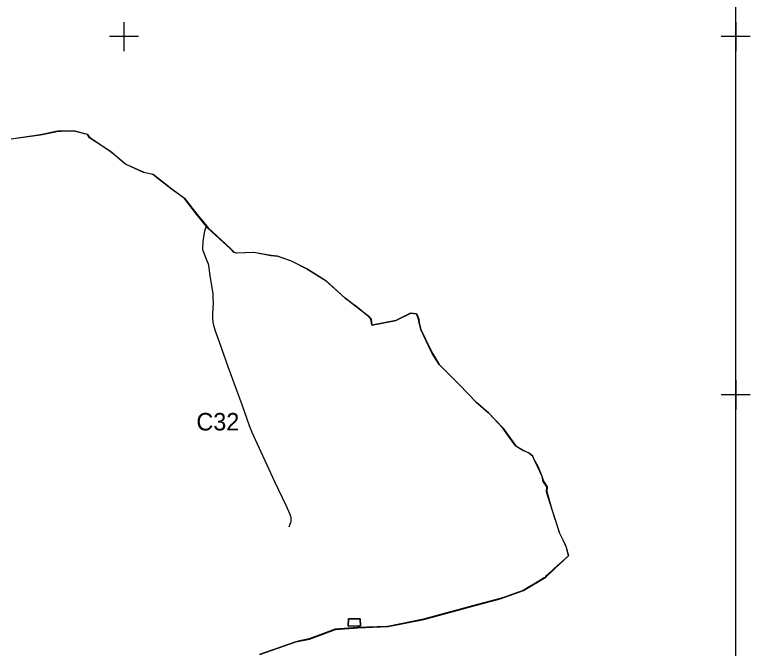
# Model space of a CAD drawing. Extents: x -478490 to -472450, y -1118050 to -1109550.
# Drawn here: x -474975 to -472450, y -1115900 to -1113725 of the extents above; entities that cross this region are included whole.
import ezdxf

# ---------------------------------------------------------------- set-up
doc = ezdxf.new("R2010")
doc.units = 0
for name, color, linetype in [('hranice kú', 7, 'Continuous'), ('Implicitní', 7, 'Continuous'), ('ObPÚ', 7, 'Continuous')]:
    doc.layers.add(name, color=color, linetype=linetype)

msp = doc.modelspace()

# ---------------------------------------------------------------- linework, layer by layer
at = {"layer": 'hranice kú'}
for p, q in [((-474772, -1114123.9), (-474828.5, -1114124.9)), ((-474725.6, -1114136), (-474772, -1114123.9)), ((-474886, -1114137.7), (-474987.2, -1114152.5)), ((-474828.5, -1114124.9), (-474886, -1114137.7)), ((-474718.2, -1114148.1), (-474725.6, -1114136)), ((-474646.3, -1114194.8), (-474718.2, -1114148.1)), ((-474595.2, -1114238.2), (-474646.3, -1114194.8)), ((-474533.5, -1114266.7), (-474595.2, -1114238.2)), ((-474500.2, -1114273.4), (-474533.5, -1114266.7)), ((-474436, -1114323.8), (-474500.2, -1114273.4)), ((-474392.1, -1114355.8), (-474436, -1114323.8)), ((-474351.1, -1114410.2), (-474392.1, -1114355.8)), ((-474312.1, -1114458.1), (-474351.1, -1114410.2)), ((-474234.1, -1114528.4), (-474312.1, -1114458.1)), ((-474222.7, -1114541.2), (-474234.1, -1114528.4)), ((-474214.6, -1114544.2), (-474222.7, -1114541.2)), ((-474155.1, -1114541.5), (-474214.6, -1114544.2)), ((-474095.2, -1114552.2), (-474155.1, -1114541.5)), ((-474072.7, -1114554.2), (-474095.2, -1114552.2)), ((-474025.3, -1114571.1), (-474072.7, -1114554.2)), ((-473972.5, -1114598), (-474025.3, -1114571.1)), ((-473907.3, -1114639), (-473972.5, -1114598)), ((-473840.6, -1114698.6), (-473907.3, -1114639)), ((-473807, -1114724.1), (-473840.6, -1114698.6)), ((-473760, -1114761.1), (-473807, -1114724.1)), ((-473616.5, -1114749.9), (-473666.9, -1114774.4)), ((-473595.9, -1114752.2), (-473616.5, -1114749.9)), ((-473588.6, -1114770.3), (-473595.9, -1114752.2)), ((-473752.6, -1114770.7), (-473760, -1114761.1)), ((-473748.8, -1114790.3), (-473752.6, -1114770.7)), ((-473666.9, -1114774.4), (-473748.8, -1114790.3)), ((-473587, -1114782.1), (-473588.6, -1114770.3)), ((-473581.1, -1114806.2), (-473587, -1114782.1)), ((-473565.4, -1114840.2), (-473581.1, -1114806.2)), ((-473541.9, -1114887.9), (-473565.4, -1114840.2)), ((-473518.4, -1114925.3), (-473541.9, -1114887.9)), ((-473447.1, -1114996.9), (-473518.4, -1114925.3)), ((-473390.3, -1115055.8), (-473447.1, -1114996.9)), ((-473347.2, -1115093.3), (-473390.3, -1115055.8)), ((-473299.1, -1115144.4), (-473347.2, -1115093.3)), ((-473261.8, -1115197.2), (-473299.1, -1115144.4)), ((-473254.4, -1115206.6), (-473261.8, -1115197.2)), ((-473230.6, -1115220.7), (-473254.4, -1115206.6)), ((-473209.4, -1115230.8), (-473230.6, -1115220.7)), ((-473197.9, -1115239.5), (-473209.4, -1115230.8)), ((-473191.9, -1115251.7), (-473197.9, -1115239.5)), ((-473180.1, -1115275.5), (-473191.9, -1115251.7)), ((-473165, -1115309.9), (-473180.1, -1115275.5)), ((-473160.6, -1115327.4), (-473165, -1115309.9)), ((-473148.9, -1115345.9), (-473160.6, -1115327.4)), ((-473149.2, -1115363.1), (-473148.9, -1115345.9)), ((-473130.7, -1115424.9), (-473149.2, -1115363.1)), ((-473119.6, -1115455.5), (-473130.7, -1115424.9)), ((-473104.5, -1115503.7), (-473119.6, -1115455.5)), ((-473092.7, -1115529.3), (-473104.5, -1115503.7)), ((-473081.3, -1115554.2), (-473092.7, -1115529.3)), ((-473073.6, -1115582.8), (-473081.3, -1115554.2)), ((-473122.6, -1115627.2), (-473073.6, -1115582.8)), ((-473152.2, -1115655.7), (-473122.6, -1115627.2)), ((-473228.9, -1115701.8), (-473152.2, -1115655.7)), ((-473308.3, -1115730.5), (-473228.9, -1115701.8)), ((-473402.8, -1115755.4), (-473308.3, -1115730.5)), ((-473570.6, -1115801.1), (-473402.8, -1115755.4)), ((-473693.7, -1115825.7), (-473570.6, -1115801.1)), ((-473963.2, -1115868.4), (-473874.4, -1115835.4)), ((-473874.4, -1115835.4), (-473797.2, -1115830.4)), ((-473797.2, -1115830.4), (-473693.7, -1115825.7)), ((-474134.2, -1115921.7), (-474010.2, -1115878.5)), ((-474010.2, -1115878.5), (-473963.2, -1115868.4))]:
    msp.add_line(p, q, dxfattribs=at)
at = {"layer": 'Implicitní'}
for p, q in [((-474600.1, -1113750.1), (-474600.1, -1113850.1)), ((-474600.1, -1113750.1), (-474600.1, -1113850.1)), ((-474600.1, -1113750.1), (-474600.1, -1113850.1)), ((-474600.1, -1113750.1), (-474600.1, -1113850.1)), ((-474600.1, -1113750.1), (-474600.1, -1113850.1)), ((-474600.1, -1113750.1), (-474600.1, -1113850.1)), ((-474600.1, -1113750.1), (-474600.1, -1113850.1)), ((-474600.1, -1113750.1), (-474600.1, -1113850.1)), ((-474600.1, -1113750.1), (-474600.1, -1113850.1)), ((-474600.1, -1113750.1), (-474600.1, -1113850.1)), ((-474600.1, -1113750.1), (-474600.1, -1113850.1)), ((-474600.1, -1113750.1), (-474600.1, -1113850.1)), ((-474600.1, -1113750.1), (-474600.1, -1113850.1)), ((-474600.1, -1113750.1), (-474600.1, -1113850.1)), ((-474600.1, -1113750.1), (-474600.1, -1113850.1)), ((-474600.1, -1113750.1), (-474600.1, -1113850.1)), ((-474600.1, -1113750.1), (-474600.1, -1113850.1)), ((-474600.1, -1113750.1), (-474600.1, -1113850.1)), ((-474600.1, -1113750.1), (-474600.1, -1113850.1)), ((-474600.1, -1113750.1), (-474600.1, -1113850.1)), ((-474600.1, -1113750.1), (-474600.1, -1113850.1)), ((-474600.1, -1113750.1), (-474600.1, -1113850.1)), ((-474600.1, -1113750.1), (-474600.1, -1113850.1)), ((-474600.1, -1113750.1), (-474600.1, -1113850.1)), ((-474600.1, -1113750.1), (-474600.1, -1113850.1)), ((-474600.1, -1113750.1), (-474600.1, -1113850.1)), ((-474600.1, -1113750.1), (-474600.1, -1113850.1)), ((-474600.1, -1113750.1), (-474600.1, -1113850.1)), ((-474600.1, -1113750.1), (-474600.1, -1113850.1)), ((-474600.1, -1113750.1), (-474600.1, -1113850.1)), ((-474600.1, -1113750.1), (-474600.1, -1113850.1)), ((-474600.1, -1113750.1), (-474600.1, -1113850.1)), ((-474600.1, -1113750.1), (-474600.1, -1113850.1)), ((-474600.1, -1113750.1), (-474600.1, -1113850.1)), ((-474600.1, -1113750.1), (-474600.1, -1113850.1)), ((-474600.1, -1113750.1), (-474600.1, -1113850.1)), ((-474600.1, -1113750.1), (-474600.1, -1113850.1)), ((-474600.1, -1113750.1), (-474600.1, -1113850.1)), ((-474600.1, -1113750.1), (-474600.1, -1113850.1)), ((-474600.1, -1113750.1), (-474600.1, -1113850.1)), ((-474600.1, -1113750.1), (-474600.1, -1113850.1)), ((-474600.1, -1113750.1), (-474600.1, -1113850.1)), ((-474600.1, -1113750.1), (-474600.1, -1113850.1)), ((-474600.1, -1113750.1), (-474600.1, -1113850.1)), ((-474600.1, -1113750.1), (-474600.1, -1113850.1)), ((-474600.1, -1113750.1), (-474600.1, -1113850.1)), ((-474600.1, -1113750.1), (-474600.1, -1113850.1)), ((-474600.1, -1113750.1), (-474600.1, -1113850.1)), ((-474600.1, -1113750.1), (-474600.1, -1113850.1)), ((-474600.1, -1113750.1), (-474600.1, -1113850.1)), ((-474600.1, -1113750.1), (-474600.1, -1113850.1)), ((-474600.1, -1113750.1), (-474600.1, -1113850.1)), ((-474600.1, -1113750.1), (-474600.1, -1113850.1)), ((-474600.1, -1113750.1), (-474600.1, -1113850.1)), ((-474600.1, -1113750.1), (-474600.1, -1113850.1)), ((-474600.1, -1113750.1), (-474600.1, -1113850.1)), ((-474600.1, -1113750.1), (-474600.1, -1113850.1)), ((-474600.1, -1113750.1), (-474600.1, -1113850.1)), ((-474600.1, -1113750.1), (-474600.1, -1113850.1)), ((-474600.1, -1113750.1), (-474600.1, -1113850.1)), ((-474600.1, -1113750.1), (-474600.1, -1113850.1)), ((-472500.1, -1113750.1), (-472500.1, -1113850.1)), ((-472500.1, -1113750.1), (-472500.1, -1113850.1)), ((-472500.1, -1113750.1), (-472500.1, -1113850.1)), ((-472500.1, -1113750.1), (-472500.1, -1113850.1)), ((-472500.1, -1113750.1), (-472500.1, -1113850.1)), ((-472500.1, -1113750.1), (-472500.1, -1113850.1)), ((-472500.1, -1113750.1), (-472500.1, -1113850.1)), ((-472500.1, -1113750.1), (-472500.1, -1113850.1)), ((-472500.1, -1113750.1), (-472500.1, -1113850.1)), ((-472500.1, -1113750.1), (-472500.1, -1113850.1)), ((-472500.1, -1113750.1), (-472500.1, -1113850.1)), ((-472500.1, -1113750.1), (-472500.1, -1113850.1)), ((-472500.1, -1113750.1), (-472500.1, -1113850.1)), ((-472500.1, -1113750.1), (-472500.1, -1113850.1)), ((-472500.1, -1113750.1), (-472500.1, -1113850.1)), ((-472500.1, -1113750.1), (-472500.1, -1113850.1)), ((-472500.1, -1113750.1), (-472500.1, -1113850.1)), ((-472500.1, -1113750.1), (-472500.1, -1113850.1)), ((-472500.1, -1113750.1), (-472500.1, -1113850.1)), ((-472500.1, -1113750.1), (-472500.1, -1113850.1)), ((-472500.1, -1113750.1), (-472500.1, -1113850.1)), ((-472500.1, -1113750.1), (-472500.1, -1113850.1)), ((-472500.1, -1113750.1), (-472500.1, -1113850.1)), ((-472500.1, -1113750.1), (-472500.1, -1113850.1)), ((-474550.1, -1113800.1), (-474650.1, -1113800.1)), ((-474550.1, -1113800.1), (-474650.1, -1113800.1)), ((-474550.1, -1113800.1), (-474650.1, -1113800.1)), ((-474550.1, -1113800.1), (-474650.1, -1113800.1)), ((-474550.1, -1113800.1), (-474650.1, -1113800.1)), ((-474550.1, -1113800.1), (-474650.1, -1113800.1)), ((-474550.1, -1113800.1), (-474650.1, -1113800.1)), ((-474550.1, -1113800.1), (-474650.1, -1113800.1)), ((-474550.1, -1113800.1), (-474650.1, -1113800.1)), ((-474550.1, -1113800.1), (-474650.1, -1113800.1)), ((-474550.1, -1113800.1), (-474650.1, -1113800.1)), ((-474550.1, -1113800.1), (-474650.1, -1113800.1)), ((-474550.1, -1113800.1), (-474650.1, -1113800.1)), ((-474550.1, -1113800.1), (-474650.1, -1113800.1)), ((-474550.1, -1113800.1), (-474650.1, -1113800.1)), ((-474550.1, -1113800.1), (-474650.1, -1113800.1)), ((-474550.1, -1113800.1), (-474650.1, -1113800.1)), ((-474550.1, -1113800.1), (-474650.1, -1113800.1)), ((-474550.1, -1113800.1), (-474650.1, -1113800.1)), ((-474550.1, -1113800.1), (-474650.1, -1113800.1)), ((-474550.1, -1113800.1), (-474650.1, -1113800.1)), ((-474550.1, -1113800.1), (-474650.1, -1113800.1)), ((-474550.1, -1113800.1), (-474650.1, -1113800.1)), ((-474550.1, -1113800.1), (-474650.1, -1113800.1)), ((-474550.1, -1113800.1), (-474650.1, -1113800.1)), ((-474550.1, -1113800.1), (-474650.1, -1113800.1)), ((-474550.1, -1113800.1), (-474650.1, -1113800.1)), ((-474550.1, -1113800.1), (-474650.1, -1113800.1)), ((-474550.1, -1113800.1), (-474650.1, -1113800.1)), ((-474550.1, -1113800.1), (-474650.1, -1113800.1)), ((-474550.1, -1113800.1), (-474650.1, -1113800.1)), ((-474550.1, -1113800.1), (-474650.1, -1113800.1)), ((-474550.1, -1113800.1), (-474650.1, -1113800.1)), ((-474550.1, -1113800.1), (-474650.1, -1113800.1)), ((-474550.1, -1113800.1), (-474650.1, -1113800.1)), ((-474550.1, -1113800.1), (-474650.1, -1113800.1)), ((-474550.1, -1113800.1), (-474650.1, -1113800.1)), ((-474550.1, -1113800.1), (-474650.1, -1113800.1)), ((-474550.1, -1113800.1), (-474650.1, -1113800.1)), ((-474550.1, -1113800.1), (-474650.1, -1113800.1)), ((-474550.1, -1113800.1), (-474650.1, -1113800.1)), ((-474550.1, -1113800.1), (-474650.1, -1113800.1)), ((-474550.1, -1113800.1), (-474650.1, -1113800.1)), ((-474550.1, -1113800.1), (-474650.1, -1113800.1)), ((-474550.1, -1113800.1), (-474650.1, -1113800.1)), ((-474550.1, -1113800.1), (-474650.1, -1113800.1)), ((-474550.1, -1113800.1), (-474650.1, -1113800.1)), ((-474550.1, -1113800.1), (-474650.1, -1113800.1)), ((-474550.1, -1113800.1), (-474650.1, -1113800.1)), ((-474550.1, -1113800.1), (-474650.1, -1113800.1)), ((-474550.1, -1113800.1), (-474650.1, -1113800.1)), ((-474550.1, -1113800.1), (-474650.1, -1113800.1)), ((-474550.1, -1113800.1), (-474650.1, -1113800.1)), ((-474550.1, -1113800.1), (-474650.1, -1113800.1)), ((-474550.1, -1113800.1), (-474650.1, -1113800.1)), ((-474550.1, -1113800.1), (-474650.1, -1113800.1)), ((-474550.1, -1113800.1), (-474650.1, -1113800.1)), ((-474550.1, -1113800.1), (-474650.1, -1113800.1)), ((-474550.1, -1113800.1), (-474650.1, -1113800.1)), ((-474550.1, -1113800.1), (-474650.1, -1113800.1)), ((-472450.1, -1113800.1), (-472550.1, -1113800.1)), ((-472450.1, -1113800.1), (-472550.1, -1113800.1)), ((-472450.1, -1113800.1), (-472550.1, -1113800.1)), ((-472450.1, -1113800.1), (-472550.1, -1113800.1)), ((-472450.1, -1113800.1), (-472550.1, -1113800.1)), ((-472450.1, -1113800.1), (-472550.1, -1113800.1)), ((-472450.1, -1113800.1), (-472550.1, -1113800.1)), ((-472450.1, -1113800.1), (-472550.1, -1113800.1)), ((-472450.1, -1113800.1), (-472550.1, -1113800.1)), ((-472450.1, -1113800.1), (-472550.1, -1113800.1)), ((-472450.1, -1113800.1), (-472550.1, -1113800.1)), ((-472450.1, -1113800.1), (-472550.1, -1113800.1)), ((-472450.1, -1113800.1), (-472550.1, -1113800.1)), ((-472450.1, -1113800.1), (-472550.1, -1113800.1)), ((-472450.1, -1113800.1), (-472550.1, -1113800.1)), ((-472450.1, -1113800.1), (-472550.1, -1113800.1)), ((-472450.1, -1113800.1), (-472550.1, -1113800.1)), ((-472450.1, -1113800.1), (-472550.1, -1113800.1)), ((-472450.1, -1113800.1), (-472550.1, -1113800.1)), ((-472450.1, -1113800.1), (-472550.1, -1113800.1)), ((-472450.1, -1113800.1), (-472550.1, -1113800.1)), ((-472450.1, -1113800.1), (-472550.1, -1113800.1)), ((-472450.1, -1113800.1), (-472550.1, -1113800.1)), ((-472450.1, -1113800.1), (-472550.1, -1113800.1)), ((-472500.1, -1114980.1), (-472500.1, -1115080.1)), ((-472500.1, -1114980.1), (-472500.1, -1115080.1)), ((-472500.1, -1114980.1), (-472500.1, -1115080.1)), ((-472500.1, -1114980.1), (-472500.1, -1115080.1)), ((-472500.1, -1114980.1), (-472500.1, -1115080.1)), ((-472500.1, -1114980.1), (-472500.1, -1115080.1)), ((-472500.1, -1114980.1), (-472500.1, -1115080.1)), ((-472500.1, -1114980.1), (-472500.1, -1115080.1)), ((-472500.1, -1114980.1), (-472500.1, -1115080.1)), ((-472500.1, -1114980.1), (-472500.1, -1115080.1)), ((-472450.1, -1115030.1), (-472550.1, -1115030.1)), ((-472450.1, -1115030.1), (-472550.1, -1115030.1)), ((-472450.1, -1115030.1), (-472550.1, -1115030.1)), ((-472450.1, -1115030.1), (-472550.1, -1115030.1)), ((-472450.1, -1115030.1), (-472550.1, -1115030.1)), ((-472450.1, -1115030.1), (-472550.1, -1115030.1)), ((-472450.1, -1115030.1), (-472550.1, -1115030.1)), ((-472450.1, -1115030.1), (-472550.1, -1115030.1)), ((-472450.1, -1115030.1), (-472550.1, -1115030.1)), ((-472450.1, -1115030.1), (-472550.1, -1115030.1))]:
    msp.add_line(p, q, dxfattribs=at)
msp.add_lwpolyline([(-478440.1, -1118000.1), (-472500.1, -1118000.1), (-472500.1, -1109600.1), (-478440.1, -1109600.1)], close=True, dxfattribs=at)
msp.add_lwpolyline([(-474317.1, -1114449), (-474323.4, -1114468), (-474326.2, -1114480.7), (-474329.6, -1114503.5), (-474330.2, -1114528.9), (-474328.9, -1114534.4), (-474318.8, -1114560.4), (-474311.3, -1114580), (-474308.3, -1114593.2), (-474306.2, -1114613.1), (-474295.4, -1114683.4), (-474294.5, -1114694.2), (-474294.4, -1114716.4), (-474296.3, -1114751.1), (-474296.3, -1114766.2), (-474294.9, -1114781.1), (-474291.9, -1114795.9), (-474287.5, -1114810.2), (-474273.8, -1114848), (-474243, -1114932.9), (-474214.9, -1115010.4), (-474195.9, -1115063), (-474169.8, -1115134.9), (-474161, -1115158.2), (-474149.5, -1115183.8), (-474082.9, -1115327), (-474044.9, -1115408.7), (-474030.3, -1115440.1), (-474029, -1115443.5), (-474028.1, -1115446.7), (-474027.5, -1115452.8), (-474027.2, -1115461.5), (-474027.8, -1115465.9), (-474030.6, -1115474.7), (-474033.9, -1115484)], dxfattribs=at)
at = {"layer": 'ObPÚ'}
for points in [[(-474987.5, -1114151), (-474886.4, -1114137.2), (-474835.2, -1114126.7), (-474826.9, -1114125), (-474813.9, -1114124.6), (-474777.6, -1114123.6), (-474775.1, -1114123.6), (-474772.3, -1114123.5)], [(-474772.3, -1114123.5), (-474725.8, -1114135.5), (-474718.4, -1114145.5), (-474708.6, -1114152.2), (-474646.9, -1114193.6), (-474635.8, -1114203), (-474630.5, -1114207.4), (-474607.9, -1114226.4), (-474597.8, -1114234.9), (-474595.5, -1114236.8), (-474532.2, -1114265.4), (-474500.7, -1114272.8), (-474483.7, -1114286), (-474436.4, -1114322.7), (-474392.2, -1114354.3), (-474385.2, -1114363.5), (-474350.2, -1114409.6), (-474320.4, -1114445), (-474314.7, -1114451.8), (-474310.6, -1114456.4), (-474234.2, -1114527.1), (-474221.3, -1114540), (-474214.3, -1114543), (-474154.8, -1114540.7), (-474095.4, -1114551.7), (-474072.2, -1114554), (-474026, -1114569.9), (-473972.3, -1114596.9), (-473906.1, -1114638.9), (-473840.6, -1114697.7), (-473832.2, -1114704.2), (-473830.5, -1114705.3), (-473821.5, -1114711.8), (-473813.9, -1114717.2), (-473805.4, -1114723.4), (-473759.3, -1114760.8), (-473751.6, -1114770.6), (-473749, -1114791.2), (-473666.9, -1114774.8), (-473615.4, -1114750.1), (-473595.3, -1114752.3), (-473588.2, -1114770.8), (-473587, -1114781.7), (-473580.8, -1114805.5), (-473565.2, -1114839.4), (-473540.1, -1114888.9), (-473517.9, -1114925.6), (-473460.9, -1114982.6), (-473458.1, -1114985.3), (-473448, -1114996.1), (-473392, -1115054.4), (-473348.2, -1115091.4), (-473299.5, -1115143.1), (-473262, -1115195.9), (-473255, -1115205.5), (-473229.4, -1115220.1), (-473209.5, -1115230.1), (-473198.2, -1115239.4), (-473192.6, -1115250.5), (-473179.5, -1115274.9), (-473165.6, -1115309), (-473160.2, -1115326.9), (-473147.9, -1115345.8), (-473148.5, -1115362.4), (-473131, -1115423.7), (-473121.6, -1115455.3), (-473104.7, -1115504.7), (-473092.8, -1115530), (-473085.6, -1115545), (-473081.6, -1115553.4), (-473080.7, -1115557.3), (-473073.7, -1115583.2), (-473122.8, -1115626.6), (-473147.5, -1115648.9), (-473153.4, -1115654.2), (-473153.1, -1115656.1), (-473157.3, -1115658.6), (-473193.3, -1115680.1), (-473214.3, -1115692.6), (-473230.3, -1115702), (-473249.2, -1115708.7), (-473268.9, -1115715.5), (-473294.2, -1115724.5), (-473309.1, -1115729.7), (-473403.8, -1115754.6), (-473571.9, -1115800.5), (-473694.2, -1115825.2), (-473697.3, -1115825.4), (-473798.5, -1115829.2), (-473875.2, -1115834.7), (-473964, -1115867.8), (-474001.8, -1115875.7), (-474005.4, -1115876.6), (-474010.3, -1115877.4), (-474134.9, -1115921.2)], [(-473788.9, -1115798.7), (-473787.6, -1115823.1), (-473830.3, -1115824.7), (-473829, -1115799.5), (-473817, -1115799.2), (-473799.7, -1115798.8), (-473788.9, -1115798.7)], [(-473799.7, -1115798.8), (-473817, -1115799.2), (-473829, -1115799.5), (-473830.3, -1115824.7), (-473787.6, -1115823.1), (-473788.9, -1115798.7), (-473799.7, -1115798.8)]]:
    msp.add_lwpolyline(points, dxfattribs=at)

# ---------------------------------------------------------------- texts
at = {"layer": 'Implicitní'}
msp.add_text('C32', height=60, dxfattribs=at).set_placement((-474351.4, -1115152.3))

doc.saveas('drawing.dxf')
